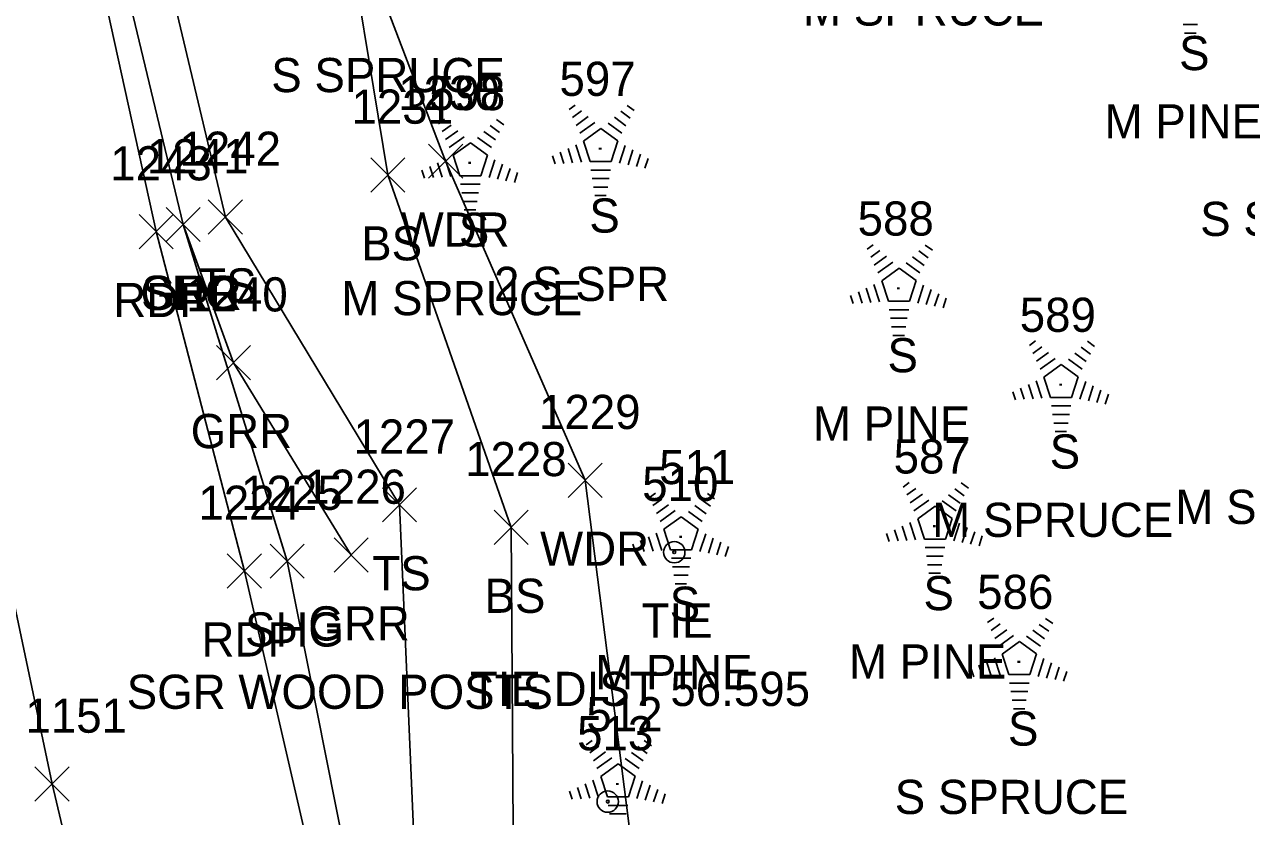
# Model space of a CAD drawing. Extents: x 1545627 to 1546562, y 571176 to 576667.
# Drawn here: x 1546146.3 to 1546217.9, y 572009.9 to 572056.2 of the extents above; entities that cross this region are included whole.
import ezdxf

# ---------------------------------------------------------------- set-up
doc = ezdxf.new("R2010")
doc.units = 0
for name, color, linetype in [('C_A', 7, 'Continuous'), ('C_C', 7, 'Continuous'), ('C_I', 7, 'Continuous'), ('CBP', 7, 'Continuous'), ('L_A', 7, 'Continuous'), ('L_C', 7, 'Continuous'), ('L_I', 7, 'Continuous'), ('L_TIC', 7, 'Continuous'), ('LAWA', 7, 'Continuous'), ('LELB', 7, 'Continuous'), ('LTC', 7, 'Continuous'), ('P_A', 7, 'Continuous'), ('P_I', 7, 'Continuous'), ('P_TIC', 7, 'Continuous'), ('PET', 7, 'Continuous'), ('PRC', 7, 'Continuous'), ('PSU', 7, 'Continuous'), ('R_A', 7, 'Continuous'), ('R_C', 7, 'Continuous'), ('R_I', 7, 'Continuous'), ('R_TIC', 7, 'Continuous'), ('RGR', 7, 'Continuous')]:
    doc.layers.add(name, color=color, linetype=linetype)

msp = doc.modelspace()

# ---------------------------------------------------------------- linework, layer by layer
at = {"layer": 'CBP'}
for centre, radius in [((1546184.335, 572025.36), 0.625), ((1546184.335, 572025.36), 0.0833), ((1546180.438, 572010.764), 0.625), ((1546180.438, 572010.764), 0.0833)]:
    msp.add_circle(centre, radius, dxfattribs=at)
at = {"layer": 'L_TIC'}
for points in [[(1546169.944, 572047.245), (1546171.944, 572049.245)], [(1546171.944, 572047.245), (1546169.944, 572049.245)], [(1546166.554, 572046.439), (1546168.554, 572048.439)], [(1546168.554, 572046.439), (1546166.554, 572048.439)], [(1546157.043, 572043.974), (1546159.043, 572045.974)], [(1546159.043, 572043.974), (1546157.043, 572045.974)], [(1546178.112, 572028.569), (1546180.112, 572030.569)], [(1546180.112, 572028.569), (1546178.112, 572030.569)], [(1546167.24, 572027.129), (1546169.24, 572029.129)], [(1546169.24, 572027.129), (1546167.24, 572029.129)], [(1546173.777, 572025.811), (1546175.777, 572027.811)], [(1546175.777, 572025.811), (1546173.777, 572027.811)]]:
    msp.add_lwpolyline(points, dxfattribs=at)
at = {"layer": 'LAWA'}
msp.add_lwpolyline([(1546228.586, 571855.541), (1546209.815, 571899.546), (1546194.552, 571952.56), (1546185.852, 571982.338), (1546183.98, 571991.384), (1546179.112, 572029.569), (1546170.944, 572048.245), (1546164.758, 572064.391), (1546155.771, 572091.279), (1546144.336, 572123.946)], dxfattribs=at)
at = {"layer": 'LELB'}
for points in [[(1546347.404, 571535.241), (1546326.62, 571574.77), (1546309.351, 571609.13), (1546297.635, 571636.432), (1546292.788, 571646.222), (1546275.729, 571689.363), (1546263.627, 571715.111), (1546250.323, 571751.347), (1546233.4, 571797.155), (1546220.817, 571841.735), (1546218.613, 571853), (1546198.39, 571897.178), (1546185.101, 571947.883), (1546175.652, 571989.222), (1546174.94, 572003.263), (1546174.777, 572026.811), (1546167.554, 572047.439), (1546164.758, 572064.391), (1546160.424, 572092.892), (1546150.118, 572129.232)], [(1546346.375, 571534.64), (1546325.48, 571574.254), (1546308.892, 571608.63), (1546296.212, 571635.99), (1546273.967, 571687.639), (1546262.69, 571714.717), (1546248.75, 571750.385), (1546231.961, 571796.63), (1546217.305, 571838.705), (1546210.358, 571854.991), (1546196.649, 571896.999), (1546182.096, 571946.809), (1546169.64, 571995.561), (1546168.24, 572028.129), (1546158.043, 572044.974), (1546148.167, 572086.529), (1546140.639, 572120.601)]]:
    msp.add_lwpolyline(points, dxfattribs=at)
at = {"layer": 'LTC'}
for p, q in [((1546214.974, 572056.237), (1546214.143, 572056.237)), ((1546214.891, 572055.737), (1546214.216, 572055.737)), ((1546178.168, 572051.273), (1546178.522, 572051.53)), ((1546178.377, 572050.807), (1546178.907, 572051.191)), ((1546181.195, 572051.165), (1546181.744, 572050.766)), ((1546181.566, 572051.513), (1546181.985, 572051.209)), ((1546170.525, 572050.44), (1546170.879, 572050.697)), ((1546170.734, 572049.974), (1546171.264, 572050.358)), ((1546173.552, 572050.332), (1546174.102, 572049.933)), ((1546173.923, 572050.68), (1546174.342, 572050.375)), ((1546178.587, 572050.341), (1546179.291, 572050.853)), ((1546178.797, 572049.876), (1546179.675, 572050.514)), ((1546180.453, 572050.468), (1546181.262, 572049.879)), ((1546180.824, 572050.816), (1546181.503, 572050.323)), ((1546170.944, 572049.508), (1546171.648, 572050.02)), ((1546171.154, 572049.043), (1546172.032, 572049.68)), ((1546172.81, 572049.635), (1546173.619, 572049.046)), ((1546173.181, 572049.983), (1546173.86, 572049.49)), ((1546179.021, 572049.421), (1546180.033, 572050.155)), ((1546180.033, 572050.155), (1546181.03, 572049.43)), ((1546171.378, 572048.588), (1546172.39, 572049.322)), ((1546172.39, 572049.322), (1546173.387, 572048.597)), ((1546177.656, 572048.769), (1546177.867, 572048.117)), ((1546178.111, 572048.985), (1546178.382, 572048.15)), ((1546178.567, 572049.201), (1546178.897, 572048.182)), ((1546179.021, 572049.421), (1546179.408, 572048.227)), ((1546181.03, 572049.43), (1546180.639, 572048.227)), ((1546181.467, 572049.159), (1546181.129, 572048.12)), ((1546181.912, 572048.909), (1546181.624, 572048.024)), ((1546170.468, 572048.152), (1546170.739, 572047.317)), ((1546170.924, 572048.368), (1546171.254, 572047.349)), ((1546171.378, 572048.588), (1546171.765, 572047.394)), ((1546173.387, 572048.597), (1546172.996, 572047.394)), ((1546173.824, 572048.326), (1546173.487, 572047.287)), ((1546174.269, 572048.076), (1546173.982, 572047.191)), ((1546177.2, 572048.552), (1546177.352, 572048.084)), ((1546180.639, 572048.227), (1546179.408, 572048.227)), ((1546182.357, 572048.659), (1546182.119, 572047.929)), ((1546182.801, 572048.409), (1546182.614, 572047.834)), ((1546169.557, 572047.719), (1546169.709, 572047.251)), ((1546170.013, 572047.935), (1546170.224, 572047.284)), ((1546172.996, 572047.394), (1546171.765, 572047.394)), ((1546174.714, 572047.826), (1546174.477, 572047.096)), ((1546175.158, 572047.575), (1546174.971, 572047.001)), ((1546180.6, 572047.727), (1546179.456, 572047.727)), ((1546172.957, 572046.894), (1546171.813, 572046.894)), ((1546180.517, 572047.227), (1546179.528, 572047.227)), ((1546180.433, 572046.727), (1546179.601, 572046.727)), ((1546172.874, 572046.394), (1546171.885, 572046.394)), ((1546172.79, 572045.894), (1546171.958, 572045.894)), ((1546180.349, 572046.227), (1546179.674, 572046.227)), ((1546172.706, 572045.394), (1546172.031, 572045.394)), ((1546195.631, 572043.098), (1546195.985, 572043.355)), ((1546199.029, 572043.338), (1546199.448, 572043.034)), ((1546195.84, 572042.632), (1546196.369, 572043.017)), ((1546196.05, 572042.167), (1546196.754, 572042.678)), ((1546196.259, 572041.701), (1546197.138, 572042.339)), ((1546198.287, 572042.642), (1546198.966, 572042.148)), ((1546198.658, 572042.99), (1546199.207, 572042.591)), ((1546196.484, 572041.246), (1546197.496, 572041.98)), ((1546197.496, 572041.98), (1546198.493, 572041.255)), ((1546197.916, 572042.293), (1546198.725, 572041.704)), ((1546196.029, 572041.027), (1546196.36, 572040.007)), ((1546196.484, 572041.246), (1546196.871, 572040.052)), ((1546198.493, 572041.255), (1546198.102, 572040.052)), ((1546198.93, 572040.984), (1546198.592, 572039.945)), ((1546194.663, 572040.377), (1546194.815, 572039.909)), ((1546195.119, 572040.594), (1546195.33, 572039.942)), ((1546195.574, 572040.81), (1546195.845, 572039.975)), ((1546199.375, 572040.734), (1546199.087, 572039.849)), ((1546199.819, 572040.484), (1546199.582, 572039.754)), ((1546200.264, 572040.234), (1546200.077, 572039.659)), ((1546198.102, 572040.052), (1546196.871, 572040.052)), ((1546198.063, 572039.552), (1546196.919, 572039.552)), ((1546197.979, 572039.052), (1546196.991, 572039.052)), ((1546197.896, 572038.552), (1546197.064, 572038.552)), ((1546197.812, 572038.052), (1546197.137, 572038.052)), ((1546205.131, 572037.465), (1546205.485, 572037.722)), ((1546205.34, 572036.999), (1546205.869, 572037.383)), ((1546208.158, 572037.357), (1546208.707, 572036.958)), ((1546208.529, 572037.705), (1546208.948, 572037.4)), ((1546205.55, 572036.533), (1546206.254, 572037.045)), ((1546205.759, 572036.068), (1546206.638, 572036.705)), ((1546207.416, 572036.66), (1546208.225, 572036.071)), ((1546207.787, 572037.008), (1546208.466, 572036.515)), ((1546205.984, 572035.613), (1546206.996, 572036.347)), ((1546206.996, 572036.347), (1546207.993, 572035.622)), ((1546205.074, 572035.177), (1546205.345, 572034.342)), ((1546205.529, 572035.393), (1546205.86, 572034.374)), ((1546205.984, 572035.613), (1546206.371, 572034.419)), ((1546207.993, 572035.622), (1546207.601, 572034.419)), ((1546208.43, 572035.351), (1546208.092, 572034.312)), ((1546204.163, 572034.744), (1546204.315, 572034.276)), ((1546204.619, 572034.96), (1546204.83, 572034.309)), ((1546208.875, 572035.101), (1546208.587, 572034.216)), ((1546209.319, 572034.851), (1546209.082, 572034.121)), ((1546209.763, 572034.6), (1546209.577, 572034.026)), ((1546207.601, 572034.419), (1546206.371, 572034.419)), ((1546207.563, 572033.919), (1546206.419, 572033.919)), ((1546207.479, 572033.419), (1546206.491, 572033.419)), ((1546207.396, 572032.919), (1546206.564, 572032.919)), ((1546207.312, 572032.419), (1546206.637, 572032.419)), ((1546197.739, 572029.174), (1546198.094, 572029.431)), ((1546182.874, 572028.552), (1546183.229, 572028.81)), ((1546186.272, 572028.793), (1546186.691, 572028.488)), ((1546197.949, 572028.708), (1546198.478, 572029.093)), ((1546198.159, 572028.243), (1546198.862, 572028.754)), ((1546200.396, 572028.718), (1546201.075, 572028.224)), ((1546200.767, 572029.066), (1546201.316, 572028.667)), ((1546201.138, 572029.414), (1546201.557, 572029.11)), ((1546183.084, 572028.087), (1546183.613, 572028.471)), ((1546183.293, 572027.621), (1546183.997, 572028.132)), ((1546185.53, 572028.096), (1546186.209, 572027.602)), ((1546185.901, 572028.444), (1546186.451, 572028.045)), ((1546198.368, 572027.777), (1546199.247, 572028.415)), ((1546198.593, 572027.322), (1546199.604, 572028.056)), ((1546199.604, 572028.056), (1546200.602, 572027.331)), ((1546200.024, 572028.369), (1546200.834, 572027.781)), ((1546183.503, 572027.155), (1546184.381, 572027.793)), ((1546183.727, 572026.7), (1546184.739, 572027.435)), ((1546184.739, 572027.435), (1546185.736, 572026.71)), ((1546185.159, 572027.748), (1546185.969, 572027.159)), ((1546198.593, 572027.322), (1546198.98, 572026.128)), ((1546200.602, 572027.331), (1546200.21, 572026.128)), ((1546183.727, 572026.7), (1546184.114, 572025.507)), ((1546185.736, 572026.71), (1546185.345, 572025.507)), ((1546197.227, 572026.67), (1546197.439, 572026.018)), ((1546197.683, 572026.886), (1546197.954, 572026.051)), ((1546198.138, 572027.103), (1546198.469, 572026.083)), ((1546201.039, 572027.061), (1546200.701, 572026.021)), ((1546201.484, 572026.81), (1546201.196, 572025.926)), ((1546201.928, 572026.56), (1546201.691, 572025.831)), ((1546182.362, 572026.048), (1546182.574, 572025.396)), ((1546182.817, 572026.265), (1546183.089, 572025.429)), ((1546183.273, 572026.481), (1546183.604, 572025.462)), ((1546186.174, 572026.439), (1546185.836, 572025.399)), ((1546186.618, 572026.188), (1546186.331, 572025.304)), ((1546187.063, 572025.938), (1546186.826, 572025.209)), ((1546196.772, 572026.453), (1546196.924, 572025.985)), ((1546200.21, 572026.128), (1546198.98, 572026.128)), ((1546202.372, 572026.31), (1546202.186, 572025.736)), ((1546181.906, 572025.831), (1546182.059, 572025.363)), ((1546185.345, 572025.507), (1546184.114, 572025.507)), ((1546187.507, 572025.688), (1546187.32, 572025.114)), ((1546200.172, 572025.628), (1546199.027, 572025.628)), ((1546200.088, 572025.128), (1546199.1, 572025.128)), ((1546185.306, 572025.007), (1546184.162, 572025.007)), ((1546185.223, 572024.507), (1546184.234, 572024.507)), ((1546200.004, 572024.628), (1546199.173, 572024.628)), ((1546185.139, 572024.007), (1546184.307, 572024.007)), ((1546199.921, 572024.128), (1546199.246, 572024.128)), ((1546185.055, 572023.507), (1546184.38, 572023.507)), ((1546202.686, 572021.246), (1546203.041, 572021.503)), ((1546202.896, 572020.78), (1546203.425, 572021.164)), ((1546205.713, 572021.138), (1546206.263, 572020.739)), ((1546206.084, 572021.486), (1546206.503, 572021.182)), ((1546203.105, 572020.314), (1546203.809, 572020.826)), ((1546203.315, 572019.849), (1546204.193, 572020.487)), ((1546203.539, 572019.394), (1546204.551, 572020.128)), ((1546204.551, 572020.128), (1546205.548, 572019.403)), ((1546204.971, 572020.441), (1546205.781, 572019.852)), ((1546205.342, 572020.789), (1546206.021, 572020.296)), ((1546205.548, 572019.403), (1546205.157, 572018.2)), ((1546202.174, 572018.742), (1546202.386, 572018.09)), ((1546202.629, 572018.958), (1546202.901, 572018.123)), ((1546203.085, 572019.174), (1546203.416, 572018.155)), ((1546203.539, 572019.394), (1546203.926, 572018.2)), ((1546205.986, 572019.132), (1546205.648, 572018.093)), ((1546206.43, 572018.882), (1546206.143, 572017.997)), ((1546201.718, 572018.525), (1546201.871, 572018.057)), ((1546205.157, 572018.2), (1546203.926, 572018.2)), ((1546206.875, 572018.632), (1546206.638, 572017.902)), ((1546207.319, 572018.382), (1546207.132, 572017.807)), ((1546205.118, 572017.7), (1546203.974, 572017.7)), ((1546205.035, 572017.2), (1546204.046, 572017.2)), ((1546204.951, 572016.7), (1546204.119, 572016.7)), ((1546204.867, 572016.2), (1546204.192, 572016.2)), ((1546179.174, 572014.09), (1546179.528, 572014.348)), ((1546179.383, 572013.625), (1546179.912, 572014.009)), ((1546182.201, 572013.982), (1546182.75, 572013.583)), ((1546182.572, 572014.331), (1546182.991, 572014.026)), ((1546179.593, 572013.159), (1546180.297, 572013.67)), ((1546179.802, 572012.693), (1546180.681, 572013.331)), ((1546180.027, 572012.238), (1546181.039, 572012.973)), ((1546181.039, 572012.973), (1546182.036, 572012.248)), ((1546181.459, 572013.286), (1546182.268, 572012.697)), ((1546181.83, 572013.634), (1546182.509, 572013.14)), ((1546182.036, 572012.248), (1546181.644, 572011.045)), ((1546178.662, 572011.586), (1546178.873, 572010.935)), ((1546179.117, 572011.803), (1546179.388, 572010.967)), ((1546179.572, 572012.019), (1546179.903, 572011)), ((1546180.027, 572012.238), (1546180.414, 572011.045)), ((1546182.473, 572011.977), (1546182.135, 572010.937)), ((1546182.918, 572011.727), (1546182.63, 572010.842)), ((1546178.206, 572011.37), (1546178.358, 572010.902)), ((1546181.644, 572011.045), (1546180.414, 572011.045)), ((1546183.362, 572011.477), (1546183.125, 572010.747)), ((1546183.806, 572011.226), (1546183.62, 572010.652)), ((1546181.606, 572010.545), (1546180.462, 572010.545)), ((1546181.522, 572010.045), (1546180.534, 572010.045))]:
    msp.add_line(p, q, dxfattribs=at)
at = {"layer": 'P_TIC'}
for points in [[(1546154.575, 572043.541), (1546156.575, 572045.541)], [(1546156.575, 572043.541), (1546154.575, 572045.541)], [(1546152.989, 572043.121), (1546154.989, 572045.121)], [(1546154.989, 572043.121), (1546152.989, 572045.121)], [(1546158.154, 572023.255), (1546160.154, 572025.255)], [(1546160.154, 572023.255), (1546158.154, 572025.255)], [(1546160.656, 572023.838), (1546162.656, 572025.838)], [(1546162.656, 572023.838), (1546160.656, 572025.838)], [(1546146.892, 572010.795), (1546148.892, 572012.795)], [(1546148.892, 572010.795), (1546146.892, 572012.795)]]:
    msp.add_lwpolyline(points, dxfattribs=at)
at = {"layer": 'PET'}
msp.add_lwpolyline([(1546178.724, 571945.469), (1546165.665, 571996.104), (1546159.154, 572024.255), (1546153.989, 572044.121), (1546144.875, 572085.592), (1546137.672, 572117.642)], dxfattribs=at)
at = {"layer": 'PRC'}
msp.add_lwpolyline([(1546157.434, 571971.538), (1546147.892, 572011.795), (1546142.502, 572037.302), (1546134.127, 572076.488), (1546128.258, 572103.577)], dxfattribs=at)
at = {"layer": 'PSU'}
msp.add_lwpolyline([(1546344.909, 571533.751), (1546324.237, 571573.752), (1546307.569, 571607.607), (1546295.255, 571635.337), (1546272.392, 571686.555), (1546261.3, 571714.23), (1546246.813, 571749.297), (1546229.824, 571796.031), (1546214.931, 571836.379), (1546208.219, 571856.105), (1546194.623, 571896.648), (1546180.076, 571945.808), (1546167.396, 571995.967), (1546161.656, 572024.838), (1546155.575, 572044.541)], dxfattribs=at)
at = {"layer": 'R_TIC'}
for points in [[(1546154.575, 572043.541), (1546156.575, 572045.541)], [(1546156.575, 572043.541), (1546154.575, 572045.541)], [(1546157.523, 572035.45), (1546159.523, 572037.45)], [(1546159.523, 572035.45), (1546157.523, 572037.45)], [(1546164.414, 572024.193), (1546166.414, 572026.193)], [(1546166.414, 572024.193), (1546164.414, 572026.193)]]:
    msp.add_lwpolyline(points, dxfattribs=at)
at = {"layer": 'RGR'}
msp.add_lwpolyline([(1546165.414, 572025.193), (1546158.523, 572036.45), (1546155.575, 572044.541), (1546145.635, 572085.932), (1546137.816, 572118.618)], dxfattribs=at)

# ---------------------------------------------------------------- texts
at = {"layer": 'C_A'}
msp.add_text('TIE', height=2, dxfattribs=at).set_placement((1546182.414, 572020.36))
at = {"layer": 'C_C'}
msp.add_text('TIE DIST 56.595', height=2, dxfattribs=at).set_placement((1546172.367, 572016.36))
at = {"layer": 'C_I'}
for s, p in [('510', (1546182.454, 572028.36)), ('513', (1546178.643, 572013.764))]:
    msp.add_text(s, height=2, dxfattribs=at).set_placement(p)
at = {"layer": 'L_A'}
for s, p in [('S', (1546213.9, 572053.574)), ('S', (1546179.358, 572044.065)), ('WDR', (1546168.306, 572043.245)), ('S', (1546171.716, 572043.231)), ('BS', (1546165.995, 572042.439)), ('TS', (1546156.453, 572039.974)), ('S', (1546196.821, 572035.89)), ('S', (1546206.321, 572030.256)), ('WDR', (1546176.474, 572024.569)), ('TS', (1546166.649, 572023.129)), ('BS', (1546173.218, 572021.811)), ('S', (1546198.93, 572021.966)), ('S', (1546184.065, 572021.344)), ('S', (1546203.877, 572014.038))]:
    msp.add_text(s, height=2, dxfattribs=at).set_placement(p)
at = {"layer": 'L_C'}
for s, p in [('M SPRUCE', (1546191.873, 572056.184)), ('S SPRUCE', (1546160.73, 572052.286)), ('M PINE', (1546209.538, 572049.574)), ('S SPRUCE', (1546215.137, 572043.869)), ('2 S SPR', (1546173.776, 572040.065)), ('M SPRUCE', (1546164.834, 572039.231)), ('M PINE', (1546192.459, 572031.89)), ('M SPRUCE', (1546213.682, 572027.011)), ('M SPRUCE', (1546199.439, 572026.256)), ('M PINE', (1546194.568, 572017.966)), ('M PINE', (1546179.702, 572017.344)), ('S SPRUCE', (1546197.247, 572010.038))]:
    msp.add_text(s, height=2, dxfattribs=at).set_placement(p)
at = {"layer": 'L_I'}
for s, p in [('597', (1546177.61, 572052.065)), ('1230', (1546168.164, 572051.245)), ('598', (1546169.968, 572051.231)), ('1231', (1546165.428, 572050.439)), ('1242', (1546155.35, 572047.974)), ('588', (1546195.073, 572043.89)), ('589', (1546204.565, 572038.256)), ('1229', (1546176.411, 572032.569)), ('1227', (1546165.547, 572031.129)), ('1228', (1546172.084, 572029.811)), ('587', (1546197.182, 572029.966)), ('511', (1546183.45, 572029.344)), ('586', (1546202.073, 572022.038)), ('512', (1546179.183, 572014.882))]:
    msp.add_text(s, height=2, dxfattribs=at).set_placement(p)
at = {"layer": 'LTC'}
for p in [(1546179.915, 572049.169), (1546172.272, 572048.335), (1546197.378, 572040.994), (1546206.878, 572035.36), (1546199.487, 572027.07), (1546184.621, 572026.448), (1546204.433, 572019.142), (1546180.921, 572011.986)]:
    msp.add_text('.', height=1.037, rotation=270, dxfattribs=at).set_placement(p)
at = {"layer": 'P_A'}
for s, p in [('RDP', (1546151.478, 572039.121)), ('SHG', (1546153.111, 572039.541)), ('SHG', (1546159.191, 572019.838)), ('RDP', (1546156.642, 572019.255))]:
    msp.add_text(s, height=2, dxfattribs=at).set_placement(p)
at = {"layer": 'P_I'}
for s, p in [('1241', (1546153.449, 572047.541)), ('1243', (1546151.297, 572047.121)), ('1225', (1546158.963, 572027.838)), ('1224', (1546156.461, 572027.255)), ('1151', (1546146.332, 572014.795))]:
    msp.add_text(s, height=2, dxfattribs=at).set_placement(p)
at = {"layer": 'R_A'}
for p in [(1546153.064, 572039.541), (1546156.011, 572031.45), (1546162.902, 572020.193)]:
    msp.add_text('GRR', height=2, dxfattribs=at).set_placement(p)
at = {"layer": 'R_C'}
msp.add_text('SGR WOOD POSTS', height=2, dxfattribs=at).set_placement((1546152.264, 572016.193))
at = {"layer": 'R_I'}
for s, p in [('1241', (1546153.449, 572047.541)), ('1240', (1546155.744, 572039.45)), ('1226', (1546162.666, 572028.193))]:
    msp.add_text(s, height=2, dxfattribs=at).set_placement(p)

doc.saveas('drawing.dxf')
